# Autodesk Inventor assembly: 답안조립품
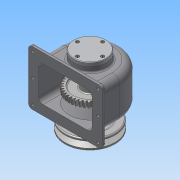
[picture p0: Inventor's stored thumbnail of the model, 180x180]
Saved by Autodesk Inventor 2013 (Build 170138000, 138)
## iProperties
Created: 2015-09
Part Number: 답안조립품
Document SubType Name: Assembly
Designer: Administrator
Author: Administrator
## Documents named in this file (14)
- C:\Users\Administrator\Desktop\450908V1018\답안조립품.iam
- C:\Users\Administrator\Desktop\450908V1018\V-벨트풀리.ipt
- C:\Users\Administrator\Desktop\450908V1018\뒤커버.ipt
- C:\Users\Administrator\Desktop\450908V1018\멈춤나사 - M4x10.ipt
- C:\Users\Administrator\Desktop\450908V1018\베어링 6203.ipt
- C:\Users\Administrator\Desktop\450908V1018\본체.ipt
- C:\Users\Administrator\Desktop\450908V1018\볼트 M3 x 8.ipt
- C:\Users\Administrator\Desktop\450908V1018\볼트 M3 x 10.ipt
- C:\Users\Administrator\Desktop\450908V1018\스퍼기어.ipt
- C:\Users\Administrator\Desktop\450908V1018\앞커버.ipt
- C:\Users\Administrator\Desktop\450908V1018\오일 실 17 32 8.ipt
- C:\Users\Administrator\Desktop\450908V1018\축.ipt
- C:\Users\Administrator\Desktop\450908V1018\키 - 5 x 5 x 18.ipt
- C:\Users\Administrator\Desktop\450908V1018\키 - 6 x 6 x 22.ipt
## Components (9 placed, 3 different names)
1. V-벨트풀리:1
2. ISO 4762 M3 x 8:1
3. ISO 4762 M3 x 8:2
4. ISO 4762 M3 x 8:3
5. ISO 4762 M3 x 8:4
6. ISO 4762 M3 x 10:1
7. ISO 4762 M3 x 10:2
8. ISO 4762 M3 x 10:3
9. ISO 4762 M3 x 10:4
